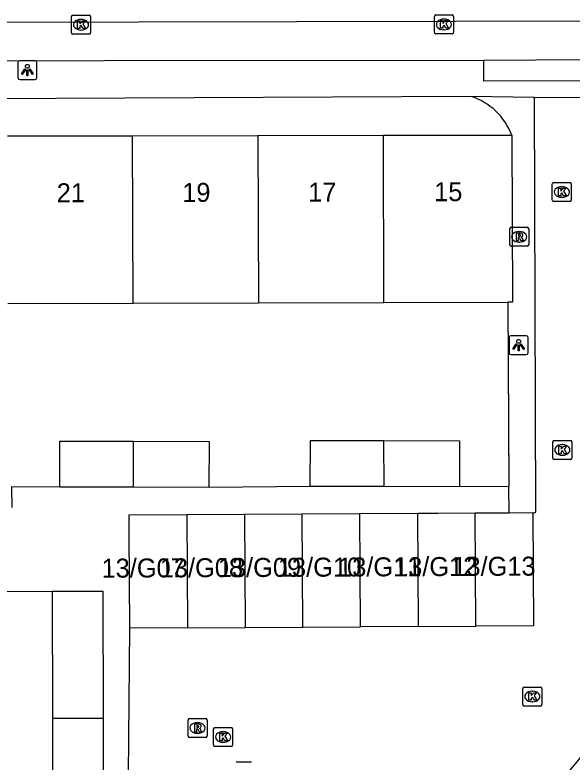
# Model space of a CAD drawing. Extents: x 160732 to 162105, y 387428 to 388479.
# Drawn here: x 161189.14 to 161218.49, y 388013.9 to 388053.28 of the extents above; entities that cross this region are included whole.
import ezdxf

# ---------------------------------------------------------------- set-up
doc = ezdxf.new("R2010")
doc.units = 0
for name, color, linetype in [('IMGEO_Kolk', 7, 'Continuous'), ('IMGEO_Lichtpunt', 7, 'Continuous'), ('IMGEO_Muur', 7, 'Continuous'), ('IMGEO_Pand', 7, 'Continuous'), ('IMGEO_Pand_nummerreeks', 7, 'Continuous'), ('IMGEO_Rijbaan_lokaal_open', 7, 'Continuous'), ('IMGEO_Rioolput', 7, 'Continuous'), ('IMGEO_Voetpad_open', 7, 'Continuous')]:
    doc.layers.add(name, color=color, linetype=linetype)

msp = doc.modelspace()

# ---------------------------------------------------------------- linework, layer by layer
at = {"layer": 'IMGEO_Kolk'}
for p, q in [((161192.118, 388052.339), (161192.118, 388053.191)), ((161192.193, 388053.265), (161193.045, 388053.265)), ((161193.119, 388053.191), (161193.119, 388052.339)), ((161211.241, 388052.353), (161211.241, 388053.205)), ((161211.316, 388053.279), (161212.168, 388053.279)), ((161212.242, 388053.205), (161212.242, 388052.353)), ((161192.606, 388053.045), (161192.631, 388053.045)), ((161211.729, 388053.059), (161211.754, 388053.059)), ((161192.629, 388052.485), (161192.604, 388052.485)), ((161211.752, 388052.499), (161211.727, 388052.499)), ((161193.045, 388052.265), (161192.193, 388052.265)), ((161212.168, 388052.279), (161211.316, 388052.279)), ((161217.528, 388044.448), (161218.38, 388044.448)), ((161217.453, 388043.522), (161217.453, 388044.374)), ((161217.941, 388044.228), (161217.966, 388044.228)), ((161218.454, 388044.374), (161218.454, 388043.522)), ((161217.964, 388043.668), (161217.939, 388043.668)), ((161218.38, 388043.448), (161217.528, 388043.448)), ((161217.48, 388029.926), (161217.48, 388030.778)), ((161217.555, 388030.852), (161218.407, 388030.852)), ((161217.968, 388030.632), (161217.993, 388030.632)), ((161218.481, 388030.778), (161218.481, 388029.926)), ((161218.407, 388029.852), (161217.555, 388029.852)), ((161217.991, 388030.072), (161217.966, 388030.072)), ((161215.899, 388016.929), (161215.899, 388017.781)), ((161215.974, 388017.855), (161216.826, 388017.855)), ((161216.387, 388017.635), (161216.412, 388017.635)), ((161216.9, 388017.781), (161216.9, 388016.929)), ((161216.826, 388016.855), (161215.974, 388016.855)), ((161216.41, 388017.075), (161216.385, 388017.075)), ((161199.68, 388015.721), (161200.532, 388015.721)), ((161199.605, 388014.795), (161199.605, 388015.647)), ((161200.093, 388015.501), (161200.118, 388015.501)), ((161200.606, 388015.647), (161200.606, 388014.795)), ((161200.116, 388014.941), (161200.091, 388014.941)), ((161200.532, 388014.721), (161199.68, 388014.721))]:
    msp.add_line(p, q, dxfattribs=at)
for points in [[(161192.118, 388052.339), (161192.118, 388053.191)], [(161192.193, 388053.265), (161193.045, 388053.265)], [(161193.119, 388053.191), (161193.119, 388052.339)], [(161211.241, 388052.353), (161211.241, 388053.205)], [(161211.316, 388053.279), (161212.168, 388053.279)], [(161212.242, 388053.205), (161212.242, 388052.353)], [(161192.439, 388052.965), (161192.562, 388052.965), (161192.562, 388052.814), (161192.692, 388052.965), (161192.856, 388052.965), (161192.71, 388052.814), (161192.863, 388052.565), (161192.711, 388052.565), (161192.626, 388052.729), (161192.562, 388052.662), (161192.562, 388052.565), (161192.439, 388052.565), (161192.439, 388052.965)], [(161211.562, 388052.979), (161211.685, 388052.979), (161211.685, 388052.828), (161211.815, 388052.979), (161211.979, 388052.979), (161211.833, 388052.828), (161211.986, 388052.579), (161211.834, 388052.579), (161211.749, 388052.743), (161211.685, 388052.676), (161211.685, 388052.579), (161211.562, 388052.579), (161211.562, 388052.979)], [(161193.045, 388052.265), (161192.193, 388052.265)], [(161212.168, 388052.279), (161211.316, 388052.279)], [(161217.528, 388044.448), (161218.38, 388044.448)], [(161217.453, 388043.522), (161217.453, 388044.374)], [(161217.774, 388044.148), (161217.897, 388044.148), (161217.897, 388043.997), (161218.027, 388044.148), (161218.191, 388044.148), (161218.045, 388043.997), (161218.198, 388043.748), (161218.046, 388043.748), (161217.961, 388043.912), (161217.897, 388043.845), (161217.897, 388043.748), (161217.774, 388043.748), (161217.774, 388044.148)], [(161218.454, 388044.374), (161218.454, 388043.522)], [(161218.38, 388043.448), (161217.528, 388043.448)], [(161217.48, 388029.926), (161217.48, 388030.778)], [(161217.555, 388030.852), (161218.407, 388030.852)], [(161218.481, 388030.778), (161218.481, 388029.926)], [(161217.801, 388030.552), (161217.924, 388030.552), (161217.924, 388030.401), (161218.054, 388030.552), (161218.218, 388030.552), (161218.072, 388030.401), (161218.225, 388030.152), (161218.073, 388030.152), (161217.988, 388030.316), (161217.924, 388030.249), (161217.924, 388030.152), (161217.801, 388030.152), (161217.801, 388030.552)], [(161218.407, 388029.852), (161217.555, 388029.852)], [(161215.899, 388016.929), (161215.899, 388017.781)], [(161215.974, 388017.855), (161216.826, 388017.855)], [(161216.9, 388017.781), (161216.9, 388016.929)], [(161216.22, 388017.555), (161216.343, 388017.555), (161216.343, 388017.404), (161216.473, 388017.555), (161216.637, 388017.555), (161216.491, 388017.404), (161216.644, 388017.155), (161216.492, 388017.155), (161216.407, 388017.319), (161216.343, 388017.252), (161216.343, 388017.155), (161216.22, 388017.155), (161216.22, 388017.555)], [(161216.826, 388016.855), (161215.974, 388016.855)], [(161199.68, 388015.721), (161200.532, 388015.721)], [(161199.605, 388014.795), (161199.605, 388015.647)], [(161199.926, 388015.421), (161200.049, 388015.421), (161200.049, 388015.27), (161200.179, 388015.421), (161200.343, 388015.421), (161200.197, 388015.27), (161200.35, 388015.021), (161200.198, 388015.021), (161200.113, 388015.185), (161200.049, 388015.118), (161200.049, 388015.021), (161199.926, 388015.021), (161199.926, 388015.421)], [(161200.606, 388015.647), (161200.606, 388014.795)], [(161200.532, 388014.721), (161199.68, 388014.721)]]:
    msp.add_lwpolyline(points, dxfattribs=at)
for centre, start, end in [((161192.195, 388053.189), 91.552, 178.448), ((161192.195, 388053.189), 91.552, 178.448), ((161193.043, 388053.189), 1.552, 88.448), ((161193.043, 388053.189), 1.552, 88.448), ((161211.318, 388053.203), 91.552, 178.448), ((161211.318, 388053.203), 91.552, 178.448), ((161212.166, 388053.203), 1.552, 88.448), ((161212.166, 388053.203), 1.552, 88.448), ((161192.195, 388052.341), 181.552, 268.448), ((161192.195, 388052.341), 181.552, 268.448), ((161193.043, 388052.341), 271.552, 358.448), ((161193.043, 388052.341), 271.552, 358.448), ((161211.318, 388052.355), 181.552, 268.448), ((161211.318, 388052.355), 181.552, 268.448), ((161212.166, 388052.355), 271.552, 358.448), ((161212.166, 388052.355), 271.552, 358.448), ((161217.53, 388044.372), 91.552, 178.448), ((161217.53, 388044.372), 91.552, 178.448), ((161218.378, 388044.372), 1.552, 88.448), ((161218.378, 388044.372), 1.552, 88.448), ((161217.53, 388043.524), 181.552, 268.448), ((161217.53, 388043.524), 181.552, 268.448), ((161218.378, 388043.524), 271.552, 358.448), ((161218.378, 388043.524), 271.552, 358.448), ((161217.557, 388030.776), 91.552, 178.448), ((161217.557, 388030.776), 91.552, 178.448), ((161218.405, 388030.776), 1.552, 88.448), ((161218.405, 388030.776), 1.552, 88.448), ((161217.557, 388029.928), 181.552, 268.448), ((161217.557, 388029.928), 181.552, 268.448), ((161218.405, 388029.928), 271.552, 358.448), ((161218.405, 388029.928), 271.552, 358.448), ((161215.976, 388017.779), 91.552, 178.448), ((161215.976, 388017.779), 91.552, 178.448), ((161216.824, 388017.779), 1.552, 88.448), ((161216.824, 388017.779), 1.552, 88.448), ((161215.976, 388016.931), 181.552, 268.448), ((161215.976, 388016.931), 181.552, 268.448), ((161216.824, 388016.931), 271.552, 358.448), ((161216.824, 388016.931), 271.552, 358.448), ((161199.682, 388015.645), 91.552, 178.448), ((161199.682, 388015.645), 91.552, 178.448), ((161200.53, 388015.645), 1.552, 88.448), ((161200.53, 388015.645), 1.552, 88.448), ((161199.682, 388014.797), 181.552, 268.448), ((161199.682, 388014.797), 181.552, 268.448), ((161200.53, 388014.797), 271.552, 358.448), ((161200.53, 388014.797), 271.552, 358.448)]:
    msp.add_arc(centre, 0.0765, start, end, dxfattribs=at)
for centre, major_axis, ratio, start_param, end_param in [((161192.605, 388052.765), (-0.387, 0.002), 0.722429, 4.712389, 7.853982), ((161192.63, 388052.765), (-0.39, 0.002), 0.717154, 1.570796, 4.712389), ((161211.728, 388052.779), (-0.387, 0.002), 0.722429, 4.712389, 7.853982), ((161211.753, 388052.779), (-0.39, 0.002), 0.717154, 1.570796, 4.712389), ((161217.94, 388043.948), (-0.387, 0.002), 0.722429, 4.712389, 7.853982), ((161217.965, 388043.948), (-0.39, 0.002), 0.717154, 1.570796, 4.712389), ((161217.967, 388030.352), (-0.387, 0.002), 0.722429, 4.712389, 7.853982), ((161217.992, 388030.352), (-0.39, 0.002), 0.717154, 1.570796, 4.712389), ((161216.386, 388017.355), (-0.387, 0.002), 0.722429, 4.712389, 7.853982), ((161216.411, 388017.355), (-0.39, 0.002), 0.717154, 1.570796, 4.712389), ((161200.092, 388015.221), (-0.387, 0.002), 0.722429, 4.712389, 7.853982), ((161200.117, 388015.221), (-0.39, 0.002), 0.717154, 1.570796, 4.712389)]:
    msp.add_ellipse(centre, major_axis=major_axis, ratio=ratio, start_param=start_param, end_param=end_param, dxfattribs=at)
at = {"layer": 'IMGEO_Lichtpunt'}
for p, q in [((161189.292, 388050.774), (161189.292, 388049.967)), ((161189.292, 388050.774), (161189.292, 388049.967)), ((161190.194, 388050.869), (161189.386, 388050.869)), ((161190.194, 388050.869), (161189.386, 388050.869)), ((161190.288, 388049.967), (161190.288, 388050.774)), ((161190.288, 388049.967), (161190.288, 388050.774)), ((161189.386, 388049.873), (161190.194, 388049.873)), ((161189.386, 388049.873), (161190.194, 388049.873)), ((161215.178, 388036.278), (161215.178, 388035.471)), ((161215.178, 388036.278), (161215.178, 388035.471)), ((161216.08, 388036.373), (161215.272, 388036.373)), ((161216.08, 388036.373), (161215.272, 388036.373)), ((161216.174, 388035.471), (161216.174, 388036.278)), ((161216.174, 388035.471), (161216.174, 388036.278)), ((161215.272, 388035.377), (161216.08, 388035.377)), ((161215.272, 388035.377), (161216.08, 388035.377)), ((161201.61, 388013.901), (161200.802, 388013.901)), ((161201.61, 388013.901), (161200.802, 388013.901))]:
    msp.add_line(p, q, dxfattribs=at)
for points in [[(161189.666, 388050.438), (161189.705, 388050.41), (161189.517, 388050.148), (161189.479, 388050.175), (161189.666, 388050.438)], [(161189.768, 388050.39), (161189.815, 388050.39), (161189.815, 388050.068), (161189.768, 388050.068), (161189.768, 388050.39)], [(161189.878, 388050.41), (161189.916, 388050.437), (161190.103, 388050.175), (161190.064, 388050.147), (161189.878, 388050.41)], [(161215.552, 388035.942), (161215.591, 388035.914), (161215.403, 388035.652), (161215.365, 388035.679), (161215.552, 388035.942)], [(161215.654, 388035.894), (161215.701, 388035.894), (161215.701, 388035.572), (161215.654, 388035.572), (161215.654, 388035.894)], [(161215.764, 388035.914), (161215.802, 388035.941), (161215.989, 388035.679), (161215.95, 388035.651), (161215.764, 388035.914)]]:
    msp.add_lwpolyline(points, dxfattribs=at)
for centre in [(161189.791, 388050.572), (161215.677, 388036.076)]:
    msp.add_circle(centre, 0.0994, dxfattribs=at)
for centre, start, end in [((161189.386, 388050.774), 90, 180), ((161189.386, 388050.774), 90, 180), ((161190.194, 388050.774), 0, 90), ((161190.194, 388050.774), 0, 90), ((161189.386, 388049.967), 180, 270), ((161189.386, 388049.967), 180, 270), ((161190.194, 388049.967), 270, 0), ((161190.194, 388049.967), 270, 360), ((161215.272, 388036.278), 90, 180), ((161215.272, 388036.278), 90, 180), ((161216.08, 388036.278), 0, 90), ((161216.08, 388036.278), 0, 90), ((161215.272, 388035.471), 180, 270), ((161215.272, 388035.471), 180, 270), ((161216.08, 388035.471), 270, 0), ((161216.08, 388035.471), 270, 360)]:
    msp.add_arc(centre, 0.0946, start, end, dxfattribs=at)
at = {"layer": 'IMGEO_Muur'}
msp.add_lwpolyline([(161215.114, 388038.133), (161215.153, 388028.49)], dxfattribs=at)
at = {"layer": 'IMGEO_Pand'}
for points in [[(161188.739, 388046.901), (161195.338, 388046.913)], [(161195.338, 388046.913), (161201.938, 388046.925)], [(161195.362, 388038.088), (161195.338, 388046.913)], [(161201.938, 388046.925), (161208.538, 388046.937)], [(161201.938, 388046.925), (161201.962, 388038.103)], [(161208.538, 388046.937), (161215.313, 388046.949)], [(161208.538, 388046.937), (161208.562, 388038.118)], [(161215.313, 388046.949), (161215.353, 388038.134), (161215.114, 388038.133)], [(161201.962, 388038.103), (161208.562, 388038.118)], [(161208.562, 388038.118), (161215.114, 388038.133)], [(161188.763, 388038.073), (161195.362, 388038.088)], [(161195.362, 388038.088), (161201.962, 388038.103)], [(161191.501, 388028.397), (161191.506, 388030.816), (161195.382, 388030.808)], [(161195.389, 388028.389), (161195.382, 388030.808)], [(161195.382, 388030.808), (161199.367, 388030.799), (161199.362, 388028.38)], [(161204.701, 388028.433), (161204.706, 388030.852), (161208.582, 388030.844)], [(161208.589, 388028.425), (161208.582, 388030.844)], [(161208.582, 388030.844), (161212.567, 388030.835), (161212.562, 388028.416)], [(161195.389, 388028.389), (161191.501, 388028.397)], [(161199.362, 388028.38), (161195.389, 388028.389)], [(161208.589, 388028.425), (161204.701, 388028.433)], [(161212.562, 388028.416), (161208.589, 388028.425)], [(161195.184, 388020.96), (161195.155, 388025.96), (161195.15, 388026.923), (161198.189, 388026.941)], [(161198.189, 388026.941), (161201.228, 388026.958)], [(161198.189, 388026.941), (161198.224, 388020.978)], [(161201.228, 388026.958), (161204.267, 388026.976)], [(161201.228, 388026.958), (161201.262, 388020.996)], [(161204.267, 388026.976), (161207.305, 388026.994)], [(161204.301, 388021.014), (161204.267, 388026.976)], [(161207.305, 388026.994), (161210.344, 388027.012)], [(161207.34, 388021.031), (161207.305, 388026.994)], [(161210.344, 388027.012), (161211.423, 388027.018), (161213.383, 388027.03)], [(161210.344, 388027.012), (161210.379, 388021.049)], [(161213.383, 388027.03), (161215.171, 388027.04)], [(161213.418, 388021.067), (161213.383, 388027.03)], [(161216.422, 388027.018), (161216.457, 388021.085), (161213.418, 388021.067)], [(161215.171, 388027.04), (161216.422, 388027.047), (161216.422, 388027.018)], [(161191.117, 388022.903), (161193.773, 388022.907), (161193.784, 388016.214)], [(161191.127, 388016.208), (161191.117, 388022.903)], [(161198.224, 388020.978), (161195.184, 388020.96)], [(161198.224, 388020.978), (161201.262, 388020.996)], [(161201.262, 388020.996), (161204.301, 388021.014)], [(161204.301, 388021.014), (161207.34, 388021.031)], [(161210.379, 388021.049), (161207.34, 388021.031)], [(161210.379, 388021.049), (161213.418, 388021.067)], [(161191.127, 388016.208), (161193.784, 388016.214)], [(161191.138, 388009.608), (161191.127, 388016.208)], [(161193.784, 388016.214), (161193.795, 388009.614)]]:
    msp.add_lwpolyline(points, dxfattribs=at)
at = {"layer": 'IMGEO_Rijbaan_lokaal_open'}
for points in [[(161262.413, 388053.043), (161170.608, 388052.85)], [(161216.422, 388027.018), (161216.589, 388027.069), (161216.511, 388048.935)], [(161216.511, 388048.935), (161219.668, 388048.943)], [(161195.119, 388013.227), (161195.184, 388020.96)]]:
    msp.add_lwpolyline(points, dxfattribs=at)
msp.add_arc((161215.439, 388016.568), 4.255, 274.4192, 354.5751, dxfattribs=at)
at = {"layer": 'IMGEO_Rioolput'}
for p, q in [((161215.282, 388042.086), (161216.134, 388042.086)), ((161215.207, 388041.16), (161215.207, 388042.012)), ((161215.695, 388041.866), (161215.72, 388041.866)), ((161216.208, 388042.012), (161216.208, 388041.16)), ((161215.718, 388041.306), (161215.693, 388041.306)), ((161216.134, 388041.086), (161215.282, 388041.086)), ((161198.256, 388015.271), (161198.256, 388016.123)), ((161198.331, 388016.197), (161199.183, 388016.197)), ((161199.257, 388016.123), (161199.257, 388015.271)), ((161198.744, 388015.977), (161198.769, 388015.977)), ((161198.767, 388015.417), (161198.742, 388015.417)), ((161199.183, 388015.197), (161198.331, 388015.197))]:
    msp.add_line(p, q, dxfattribs=at)
for points in [[(161215.282, 388042.086), (161216.134, 388042.086)], [(161215.207, 388041.16), (161215.207, 388042.012)], [(161215.796, 388041.784), (161215.544, 388041.786), (161215.544, 388041.386)], [(161215.722, 388041.705), (161215.668, 388041.705), (161215.668, 388041.624)], [(161216.208, 388042.012), (161216.208, 388041.16)], [(161215.544, 388041.386), (161215.668, 388041.386), (161215.668, 388041.548), (161215.679, 388041.548)], [(161215.668, 388041.624), (161215.72, 388041.624)], [(161215.726, 388041.519), (161215.797, 388041.386), (161215.937, 388041.386), (161215.872, 388041.512)], [(161216.134, 388041.086), (161215.282, 388041.086)], [(161198.256, 388015.271), (161198.256, 388016.123)], [(161198.331, 388016.197), (161199.183, 388016.197)], [(161199.257, 388016.123), (161199.257, 388015.271)], [(161198.845, 388015.895), (161198.593, 388015.897), (161198.593, 388015.497)], [(161198.593, 388015.497), (161198.717, 388015.497), (161198.717, 388015.659), (161198.728, 388015.659)], [(161198.771, 388015.816), (161198.717, 388015.816), (161198.717, 388015.735)], [(161198.717, 388015.735), (161198.769, 388015.735)], [(161198.775, 388015.63), (161198.846, 388015.497), (161198.986, 388015.497), (161198.921, 388015.623)], [(161199.183, 388015.197), (161198.331, 388015.197)]]:
    msp.add_lwpolyline(points, dxfattribs=at)
for centre, radius, start, end in [((161215.284, 388042.01), 0.0765, 91.552, 178.448), ((161215.284, 388042.01), 0.0765, 91.552, 178.448), ((161216.132, 388042.01), 0.0765, 1.552, 88.448), ((161216.132, 388042.01), 0.0765, 1.552, 88.448), ((161215.728, 388041.609), 0.0964, 77.0061, 93.1865), ((161215.742, 388041.666), 0.0378, 276.6634, 79.6772), ((161215.795, 388041.674), 0.109, 350.3612, 89.416), ((161215.793, 388041.674), 0.112, 277.5842, 350.9817), ((161215.678, 388041.495), 0.0533, 26.0293, 88.6989), ((161215.704, 388041.813), 0.19, 274.7715, 282.9687), ((161215.777, 388041.459), 0.108, 29.5134, 73.7905), ((161215.284, 388041.162), 0.0765, 181.552, 268.448), ((161215.284, 388041.162), 0.0765, 181.552, 268.448), ((161216.132, 388041.162), 0.0765, 271.552, 358.448), ((161216.132, 388041.162), 0.0765, 271.552, 358.448), ((161198.333, 388016.121), 0.0765, 91.552, 178.448), ((161198.333, 388016.121), 0.0765, 91.552, 178.448), ((161199.181, 388016.121), 0.0765, 1.552, 88.448), ((161199.181, 388016.121), 0.0765, 1.552, 88.448), ((161198.727, 388015.606), 0.0533, 26.0293, 88.6989), ((161198.753, 388015.924), 0.19, 274.7715, 282.9687), ((161198.777, 388015.72), 0.0964, 77.0061, 93.1865), ((161198.791, 388015.777), 0.0378, 276.6634, 79.6772), ((161198.844, 388015.785), 0.109, 350.3612, 89.416), ((161198.842, 388015.785), 0.112, 277.5842, 350.9817), ((161198.826, 388015.57), 0.108, 29.5134, 73.7905), ((161198.333, 388015.273), 0.0765, 181.552, 268.448), ((161198.333, 388015.273), 0.0765, 181.552, 268.448), ((161199.181, 388015.273), 0.0765, 271.552, 358.448), ((161199.181, 388015.273), 0.0765, 271.552, 358.448)]:
    msp.add_arc(centre, radius, start, end, dxfattribs=at)
for centre, major_axis, ratio, start_param, end_param in [((161215.694, 388041.586), (-0.387, 0.002), 0.722429, 4.712389, 7.853982), ((161215.719, 388041.586), (-0.39, 0.002), 0.717154, 1.570796, 4.712389), ((161198.743, 388015.697), (-0.387, 0.002), 0.722429, 4.712389, 7.853982), ((161198.768, 388015.697), (-0.39, 0.002), 0.717154, 1.570796, 4.712389)]:
    msp.add_ellipse(centre, major_axis=major_axis, ratio=ratio, start_param=start_param, end_param=end_param, dxfattribs=at)
at = {"layer": 'IMGEO_Voetpad_open'}
for points in [[(161213.836, 388050.887), (161173.827, 388050.837)], [(161222.055, 388050.928), (161213.836, 388050.887)], [(161222.055, 388050.928), (161222.058, 388049.802), (161213.839, 388049.782), (161213.836, 388050.887)], [(161213.161, 388048.984), (161169.409, 388048.766)], [(161216.511, 388048.935), (161213.161, 388048.984)], [(161215.114, 388038.133), (161215.154, 388028.426)], [(161191.501, 388028.397), (161188.964, 388028.402), (161188.969, 388027.311)], [(161204.701, 388028.433), (161199.362, 388028.38)], [(161215.154, 388028.426), (161212.562, 388028.416)], [(161215.171, 388027.04), (161215.154, 388028.426)], [(161183.178, 388022.893), (161191.117, 388022.903)]]:
    msp.add_lwpolyline(points, dxfattribs=at)
msp.add_arc((161212.142, 388045.751), 3.39, 20.6953, 72.506, dxfattribs=at)

# ---------------------------------------------------------------- texts
at = {"layer": 'IMGEO_Pand_nummerreeks'}
for s, rotation, p in [('21', 0.1591, (161191.338, 388043.406)), ('19', 0.1591, (161197.953, 388043.424)), ('17', 0.1591, (161204.59, 388043.442)), ('15', 0.1591, (161211.227, 388043.461)), ('13/G10', 0.2781, (161202.994, 388023.663)), ('13/G11', 0.2781, (161206.167, 388023.678)), ('13/G12', 0.2781, (161209.115, 388023.693)), ('13/G13', 0.2781, (161212.187, 388023.707)), ('13/G07', 0.2781, (161193.703, 388023.618)), ('13/G08', 0.2781, (161196.772, 388023.633)), ('13/G09', 0.2781, (161199.831, 388023.647))]:
    msp.add_text(s, height=1, rotation=rotation, dxfattribs=at).set_placement(p)

doc.saveas('drawing.dxf')
